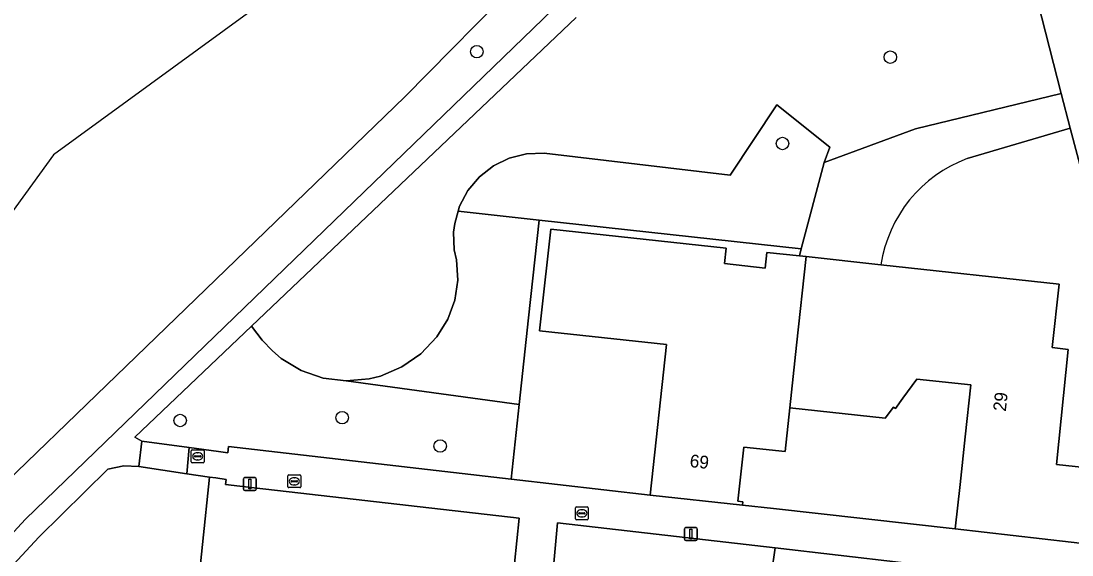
# Model space of a CAD drawing. Extents: x 162396 to 163643, y 386452 to 387406.
# Drawn here: x 162915.8 to 162998.1, y 387129.8 to 387171.5 of the extents above; entities that cross this region are included whole.
import ezdxf

# ---------------------------------------------------------------- set-up
doc = ezdxf.new("R2010")
doc.units = 0
for name, color, linetype in [('IMGEO_Boom', 7, 'Continuous'), ('IMGEO_Brandkraan', 7, 'Continuous'), ('IMGEO_Erf', 7, 'Continuous'), ('IMGEO_Groenvoorziening', 7, 'Continuous'), ('IMGEO_Lichtmast', 7, 'Continuous'), ('IMGEO_Meer_plas_ven_vijver', 7, 'Continuous'), ('IMGEO_Muur', 7, 'Continuous'), ('IMGEO_Pand', 7, 'Continuous'), ('IMGEO_Pand_nummerreeks', 7, 'Continuous'), ('IMGEO_Rioolput', 7, 'Continuous'), ('IMGEO_Voetpad_halfverhard', 7, 'Continuous'), ('IMGEO_Voetpad_open', 7, 'Continuous')]:
    doc.layers.add(name, color=color, linetype=linetype)

msp = doc.modelspace()

# ---------------------------------------------------------------- linework, layer by layer
at = {"layer": 'IMGEO_Boom'}
for centre in [(162951.492, 387169.124), (162983.842, 387168.702), (162975.411, 387161.953), (162928.28, 387140.296), (162940.961, 387140.515), (162948.63, 387138.296)]:
    msp.add_circle(centre, 0.489, dxfattribs=at)
at = {"layer": 'IMGEO_Brandkraan'}
for p, q in [((162929.155, 387137.072), (162929.155, 387137.924)), ((162929.23, 387137.998), (162930.082, 387137.998)), ((162929.414, 387137.492), (162929.414, 387137.504)), ((162929.852, 387137.455), (162929.454, 387137.455)), ((162929.457, 387137.541), (162929.855, 387137.541)), ((162929.643, 387137.778), (162929.668, 387137.778)), ((162929.898, 387137.504), (162929.898, 387137.492)), ((162930.156, 387137.924), (162930.156, 387137.072)), ((162930.082, 387136.998), (162929.23, 387136.998)), ((162929.666, 387137.218), (162929.641, 387137.218))]:
    msp.add_line(p, q, dxfattribs=at)
for points in [[(162929.155, 387137.072), (162929.155, 387137.924)], [(162929.23, 387137.998), (162930.082, 387137.998)], [(162930.156, 387137.924), (162930.156, 387137.072)], [(162930.082, 387136.998), (162929.23, 387136.998)]]:
    msp.add_lwpolyline(points, dxfattribs=at)
for centre, radius, start, end in [((162929.232, 387137.922), 0.0765, 91.55205, 178.44795), ((162929.232, 387137.922), 0.0765, 91.55205, 178.44795), ((162929.454, 387137.501), 0.0403, 85.87752, 175.75265), ((162929.451, 387137.491), 0.0366, 178.93798, 274.71019), ((162929.855, 387137.498), 0.043, 264.86636, 352.45326), ((162929.859, 387137.503), 0.0386, 1.73085, 96.63898), ((162930.08, 387137.922), 0.0765, 1.55205, 88.44795), ((162930.08, 387137.922), 0.0765, 1.55205, 88.44795), ((162929.232, 387137.074), 0.0765, 181.55205, 268.44795), ((162929.232, 387137.074), 0.0765, 181.55205, 268.44795), ((162930.08, 387137.074), 0.0765, 271.55205, 358.44795), ((162930.08, 387137.074), 0.0765, 271.55205, 358.44795)]:
    msp.add_arc(centre, radius, start, end, dxfattribs=at)
for centre, major_axis, ratio, start_param, end_param in [((162929.642, 387137.498), (-0.387, 0.002), 0.722429, 4.712389, 7.853982), ((162929.667, 387137.498), (-0.39, 0.002), 0.717154, 1.570796, 4.712389)]:
    msp.add_ellipse(centre, major_axis=major_axis, ratio=ratio, start_param=start_param, end_param=end_param, dxfattribs=at)
at = {"layer": 'IMGEO_Erf'}
for points in [[(162983.108, 387152.47), (162997.052, 387150.951), (162996.513, 387145.994), (162997.744, 387145.854), (162996.852, 387136.865), (162998.293, 387136.701), (163000.935, 387136.401), (163000.267, 387130.528), (163006.513, 387129.798), (163002.885, 387144.421), (162997.907, 387163.149)], [(162997.907, 387163.149), (162989.861, 387160.775)], [(163000, 387127.409), (162984.703, 387129.19), (162974.82, 387130.333), (162974.534, 387128.355), (162984.471, 387127.214), (162994.298, 387126.085), (162994.219, 387125.397), (162993.887, 387122.513), (162993.841, 387122.11), (162992.64, 387122.248), (162992.086, 387117.433), (162993.292, 387117.294), (162993.273, 387117.131), (162992.119, 387107.076), (162993.218, 387102.569), (162990.473, 387097.337), (162987.989, 387095.591), (162978.209, 387090.267), (162980.161, 387087.989), (162983.775, 387090.721), (162988.184, 387093.295), (162990.531, 387094.665), (163000, 387099.433)]]:
    msp.add_lwpolyline(points, dxfattribs=at)
for points in [[(162966.332, 387146.23), (162956.407, 387147.31), (162956.507, 387148.232), (162957.273, 387155.266), (162971.01, 387153.77), (162970.878, 387152.561), (162974.058, 387152.214), (162974.192, 387153.441), (162976.738, 387153.164), (162976.88, 387153.704), (162956.38, 387155.957), (162955.523, 387148.324), (162954.796, 387141.535), (162954.173, 387135.713), (162965.051, 387134.463)], [(162988.919, 387131.817), (162989.298, 387135.295), (162989.704, 387139.02), (162990.145, 387143.071), (162985.913, 387143.531), (162984.83, 387142.052), (162984.236, 387141.241), (162984.089, 387141.349), (162983.449, 387140.475), (162975.989, 387141.287), (162975.617, 387137.871), (162972.383, 387138.223), (162971.922, 387133.987), (162972.302, 387133.946), (162972.272, 387133.677), (162974.708, 387133.405)], [(162954.814, 387132.669), (162934.076, 387135.027), (162931.83, 387135.282), (162931.881, 387135.682), (162931.077, 387135.801), (162930.576, 387135.875), (162928.93, 387120.073), (162927.574, 387107.059), (162951.889, 387104.679), (162952.055, 387105.95), (162954.081, 387125.567)], [(162957.802, 387132.302), (162957.147, 387125.165), (162962.225, 387124.616), (162966.48, 387124.156), (162967.227, 387126.127), (162968.275, 387126.076), (162968.469, 387126.065), (162968.747, 387125.311), (162967.83, 387115.561), (162967.759, 387111.387), (162968.295, 387108.233), (162969.336, 387107.072), (162978.401, 387105.997), (162978.647, 387108.229), (162978.831, 387109.908), (162980.66, 387109.757), (162980.685, 387110.054), (162983.986, 387109.717), (162985.218, 387120.432), (162981.329, 387120.879), (162981.118, 387119.05), (162973.564, 387119.918), (162974.534, 387128.355), (162974.82, 387130.333)]]:
    msp.add_lwpolyline(points, close=True, dxfattribs=at)
msp.add_arc((162993.517, 387150.904), 10.526, 110.32286, 171.44632, dxfattribs=at)
at = {"layer": 'IMGEO_Groenvoorziening'}
for points in [[(162904.234, 387119.646), (162916.196, 387132.579), (162958.243, 387173.224), (162966.778, 387181.153), (162972.048, 387185.44), (162977.07, 387188.884), (162978.312, 387189.488), (162981.995, 387189.888), (162986.564, 387190.198), (162988.981, 387190.548), (162990.622, 387191.429), (162988.941, 387198.721), (162970.442, 387190.315), (162969.073, 387188.983), (162962.124, 387182.486), (162955.059, 387174.946), (162945.852, 387165.587), (162890.58, 387112.23)], [(162959.252, 387171.801), (162933.874, 387147.675), (162934.7, 387146.585), (162935.5, 387145.73), (162936.195, 387145.145), (162937.75, 387144.21), (162939.465, 387143.617), (162941.266, 387143.395), (162943.074, 387143.552), (162943.955, 387143.771), (162945.626, 387144.478), (162947.113, 387145.518), (162948.352, 387146.844), (162949.223, 387148.214), (162949.775, 387149.705), (162950.005, 387151.279), (162949.903, 387152.865), (162949.728, 387153.642), (162949.68, 387155.016), (162949.764, 387155.707), (162950.035, 387156.654), (162950.146, 387157.044), (162950.798, 387158.272), (162951.69, 387159.338), (162952.785, 387160.195), (162954.034, 387160.805), (162955.383, 387161.143), (162956.772, 387161.193), (162971.313, 387159.479), (162974.954, 387164.968), (162979.098, 387161.653), (162978.659, 387160.475), (162985.799, 387163.098), (162997.198, 387165.859), (162991.45, 387188.438)], [(162924.374, 387120.523), (162928.93, 387120.073), (162930.576, 387135.875), (162928.798, 387136.138), (162925.06, 387136.69), (162923.867, 387136.75), (162922.636, 387136.483), (162917.237, 387131.176), (162905.354, 387118.405)]]:
    msp.add_lwpolyline(points, dxfattribs=at)
for points in [[(162976.88, 387153.704), (162978.659, 387160.475), (162979.098, 387161.653), (162974.954, 387164.968), (162971.313, 387159.479), (162956.772, 387161.193), (162955.383, 387161.143), (162954.034, 387160.805), (162952.785, 387160.195), (162951.69, 387159.338), (162950.798, 387158.272), (162950.146, 387157.044), (162950.035, 387156.654), (162956.38, 387155.957)], [(162955.523, 387148.324), (162956.38, 387155.957), (162950.035, 387156.654), (162949.764, 387155.707), (162949.68, 387155.016), (162949.728, 387153.642), (162949.903, 387152.865), (162950.005, 387151.279), (162949.775, 387149.705), (162949.223, 387148.214), (162948.352, 387146.844), (162947.113, 387145.518), (162945.626, 387144.478), (162943.955, 387143.771), (162943.074, 387143.552), (162941.266, 387143.395), (162954.796, 387141.535)], [(162941.266, 387143.395), (162939.465, 387143.617), (162937.75, 387144.21), (162936.195, 387145.145), (162935.5, 387145.73), (162934.7, 387146.585), (162933.874, 387147.675), (162924.751, 387138.998), (162925.28, 387138.681), (162928.991, 387138.18), (162931.284, 387137.871), (162932.025, 387137.771), (162932.076, 387138.251), (162954.173, 387135.713), (162954.796, 387141.535)]]:
    msp.add_lwpolyline(points, close=True, dxfattribs=at)
at = {"layer": 'IMGEO_Lichtmast'}
for p, q in [((162933.336, 387135.827), (162934.126, 387135.827)), ((162934.126, 387135.827), (162933.336, 387135.827)), ((162933.236, 387134.927), (162933.236, 387135.727)), ((162933.236, 387135.727), (162933.236, 387134.927)), ((162934.226, 387135.727), (162934.226, 387134.927)), ((162934.226, 387134.927), (162934.226, 387135.727)), ((162934.126, 387134.827), (162933.336, 387134.827)), ((162933.336, 387134.827), (162934.126, 387134.827)), ((162967.749, 387131.02), (162967.749, 387131.82)), ((162967.749, 387131.82), (162967.749, 387131.02)), ((162967.849, 387131.92), (162968.639, 387131.92)), ((162968.639, 387131.92), (162967.849, 387131.92)), ((162968.739, 387131.82), (162968.739, 387131.02)), ((162968.739, 387131.02), (162968.739, 387131.82)), ((162968.639, 387130.92), (162967.849, 387130.92)), ((162967.849, 387130.92), (162968.639, 387130.92))]:
    msp.add_line(p, q, dxfattribs=at)
for points in [[(162933.656, 387135.702), (162933.806, 387135.702), (162933.806, 387134.952), (162933.656, 387134.952), (162933.656, 387135.702)], [(162968.169, 387131.795), (162968.319, 387131.795), (162968.319, 387131.045), (162968.169, 387131.045), (162968.169, 387131.795)]]:
    msp.add_lwpolyline(points, dxfattribs=at)
for centre, start, end in [((162933.336, 387135.727), 90, 180), ((162933.336, 387135.727), 90, 180), ((162934.126, 387135.727), 0, 90), ((162934.126, 387135.727), 360, 90), ((162933.336, 387134.927), 180, 270), ((162933.336, 387134.927), 180, 270), ((162934.126, 387134.927), 270, 0), ((162934.126, 387134.927), 270, 0), ((162967.849, 387131.82), 90, 180), ((162967.849, 387131.82), 90, 180), ((162968.639, 387131.82), 0, 90), ((162968.639, 387131.82), 360, 90), ((162967.849, 387131.02), 180, 270), ((162967.849, 387131.02), 180, 270), ((162968.639, 387131.02), 270, 0), ((162968.639, 387131.02), 270, 0)]:
    msp.add_arc(centre, 0.1, start, end, dxfattribs=at)
at = {"layer": 'IMGEO_Meer_plas_ven_vijver'}
msp.add_lwpolyline([(162890.58, 387112.23), (162945.852, 387165.587), (162955.059, 387174.946), (162962.124, 387182.486), (162969.073, 387188.983), (162970.442, 387190.315), (162971.638, 387191.805), (162973.104, 387194.354), (162973.352, 387194.938), (162973.548, 387195.542), (162973.688, 387196.162), (162973.773, 387196.791), (162973.801, 387197.425), (162973.772, 387198.059), (162973.686, 387198.688), (162973.682, 387198.713), (162973.321, 387201.081), (162973.321, 387201.081), (162918.383, 387161.062), (162747.703, 386925.615)], dxfattribs=at)
at = {"layer": 'IMGEO_Muur'}
for points in [[(162956.38, 387155.957), (162955.523, 387148.324)], [(162954.173, 387135.713), (162965.051, 387134.463)], [(162974.708, 387133.405), (162988.919, 387131.817)]]:
    msp.add_lwpolyline(points, dxfattribs=at)
at = {"layer": 'IMGEO_Pand'}
for points in [[(162976.738, 387153.164), (162974.192, 387153.441), (162974.058, 387152.214), (162970.878, 387152.561), (162971.01, 387153.77), (162957.273, 387155.266), (162956.507, 387148.232), (162956.407, 387147.31), (162966.332, 387146.23), (162965.051, 387134.463), (162972.272, 387133.677), (162972.302, 387133.946), (162971.922, 387133.987), (162972.383, 387138.223), (162975.617, 387137.871), (162975.989, 387141.287), (162976.5, 387146.183), (162977.254, 387153.107)], [(163000.267, 387130.528), (163000.935, 387136.401), (162998.293, 387136.701), (162996.852, 387136.865), (162997.744, 387145.854), (162996.513, 387145.994), (162997.052, 387150.951), (162983.108, 387152.47), (162977.254, 387153.107), (162976.5, 387146.183), (162975.989, 387141.287), (162983.449, 387140.475), (162984.089, 387141.349), (162984.236, 387141.241), (162984.83, 387142.052), (162985.913, 387143.531), (162990.145, 387143.071), (162989.704, 387139.02), (162989.298, 387135.295), (162988.919, 387131.817)]]:
    msp.add_lwpolyline(points, close=True, dxfattribs=at)
at = {"layer": 'IMGEO_Rioolput'}
for p, q in [((162936.713, 387135.12), (162936.713, 387135.972)), ((162936.788, 387136.046), (162937.64, 387136.046)), ((162937.201, 387135.826), (162937.226, 387135.826)), ((162937.714, 387135.972), (162937.714, 387135.12)), ((162937.64, 387135.046), (162936.788, 387135.046)), ((162936.972, 387135.54), (162936.972, 387135.552)), ((162937.41, 387135.503), (162937.012, 387135.503)), ((162937.015, 387135.589), (162937.413, 387135.589)), ((162937.224, 387135.266), (162937.199, 387135.266)), ((162937.456, 387135.552), (162937.456, 387135.54)), ((162959.211, 387132.608), (162959.211, 387133.46)), ((162959.286, 387133.534), (162960.138, 387133.534)), ((162959.699, 387133.314), (162959.724, 387133.314)), ((162960.212, 387133.46), (162960.212, 387132.608)), ((162960.138, 387132.534), (162959.286, 387132.534)), ((162959.47, 387133.028), (162959.47, 387133.04)), ((162959.908, 387132.991), (162959.51, 387132.991)), ((162959.513, 387133.077), (162959.911, 387133.077)), ((162959.722, 387132.754), (162959.697, 387132.754)), ((162959.954, 387133.04), (162959.954, 387133.028))]:
    msp.add_line(p, q, dxfattribs=at)
for points in [[(162936.713, 387135.12), (162936.713, 387135.972)], [(162936.788, 387136.046), (162937.64, 387136.046)], [(162937.714, 387135.972), (162937.714, 387135.12)], [(162937.64, 387135.046), (162936.788, 387135.046)], [(162959.211, 387132.608), (162959.211, 387133.46)], [(162959.286, 387133.534), (162960.138, 387133.534)], [(162960.212, 387133.46), (162960.212, 387132.608)], [(162960.138, 387132.534), (162959.286, 387132.534)]]:
    msp.add_lwpolyline(points, dxfattribs=at)
for centre, radius, start, end in [((162936.79, 387135.97), 0.0765, 91.55205, 178.44795), ((162936.79, 387135.97), 0.0765, 91.55205, 178.44795), ((162937.638, 387135.97), 0.0765, 1.55205, 88.44795), ((162937.638, 387135.97), 0.0765, 1.55205, 88.44795), ((162936.79, 387135.122), 0.0765, 181.55205, 268.44795), ((162936.79, 387135.122), 0.0765, 181.55205, 268.44795), ((162937.012, 387135.549), 0.0403, 85.87752, 175.75265), ((162937.009, 387135.539), 0.0366, 178.93798, 274.71019), ((162937.413, 387135.546), 0.043, 264.86636, 352.45326), ((162937.417, 387135.551), 0.0386, 1.73085, 96.63898), ((162937.638, 387135.122), 0.0765, 271.55205, 358.44795), ((162937.638, 387135.122), 0.0765, 271.55205, 358.44795), ((162959.288, 387133.458), 0.0765, 91.55205, 178.44795), ((162959.288, 387133.458), 0.0765, 91.55205, 178.44795), ((162960.136, 387133.458), 0.0765, 1.55205, 88.44795), ((162960.136, 387133.458), 0.0765, 1.55205, 88.44795), ((162959.288, 387132.61), 0.0765, 181.55205, 268.44795), ((162959.288, 387132.61), 0.0765, 181.55205, 268.44795), ((162959.51, 387133.037), 0.0403, 85.87752, 175.75265), ((162959.507, 387133.027), 0.0366, 178.93798, 274.71019), ((162959.911, 387133.034), 0.043, 264.86636, 352.45326), ((162959.915, 387133.039), 0.0386, 1.73085, 96.63898), ((162960.136, 387132.61), 0.0765, 271.55205, 358.44795), ((162960.136, 387132.61), 0.0765, 271.55205, 358.44795)]:
    msp.add_arc(centre, radius, start, end, dxfattribs=at)
for centre, major_axis, ratio, start_param, end_param in [((162937.2, 387135.546), (-0.387, 0.002), 0.722429, 4.712389, 7.853982), ((162937.225, 387135.546), (-0.39, 0.002), 0.717154, 1.570796, 4.712389), ((162959.698, 387133.034), (-0.387, 0.002), 0.722429, 4.712389, 7.853982), ((162959.723, 387133.034), (-0.39, 0.002), 0.717154, 1.570796, 4.712389)]:
    msp.add_ellipse(centre, major_axis=major_axis, ratio=ratio, start_param=start_param, end_param=end_param, dxfattribs=at)
at = {"layer": 'IMGEO_Voetpad_halfverhard'}
for points in [[(162958.243, 387173.224), (162916.196, 387132.579), (162904.234, 387119.646)], [(162905.354, 387118.405), (162917.237, 387131.176), (162922.636, 387136.483), (162923.867, 387136.75), (162925.06, 387136.69), (162925.28, 387138.681), (162924.751, 387138.998), (162933.874, 387147.675), (162959.252, 387171.801)]]:
    msp.add_lwpolyline(points, dxfattribs=at)
at = {"layer": 'IMGEO_Voetpad_open'}
for points in [[(162986.23, 387210.485), (162986.356, 387209.887), (162988.941, 387198.721), (162990.622, 387191.429), (162991.45, 387188.438), (162997.198, 387165.859), (162997.907, 387163.149), (163002.885, 387144.421), (163006.513, 387129.798), (163007.387, 387126.313), (163011.824, 387109.13)], [(162989.861, 387160.775), (162997.907, 387163.149), (162997.198, 387165.859), (162985.799, 387163.098), (162978.659, 387160.475), (162976.88, 387153.704), (162976.738, 387153.164), (162977.254, 387153.107), (162983.108, 387152.47)], [(163000.267, 387130.528), (162988.919, 387131.817), (162974.708, 387133.405), (162972.272, 387133.677), (162965.051, 387134.463), (162954.173, 387135.713), (162932.076, 387138.251), (162932.025, 387137.771), (162931.284, 387137.871), (162928.991, 387138.18), (162928.798, 387136.138), (162930.576, 387135.875), (162931.077, 387135.801), (162931.881, 387135.682), (162931.83, 387135.282), (162934.076, 387135.027), (162954.814, 387132.669), (162954.081, 387125.567), (162957.147, 387125.165), (162957.802, 387132.302), (162974.82, 387130.333), (162984.703, 387129.19), (163000, 387127.409)]]:
    msp.add_lwpolyline(points, dxfattribs=at)
msp.add_lwpolyline([(162928.991, 387138.18), (162925.28, 387138.681), (162925.06, 387136.69), (162928.798, 387136.138)], close=True, dxfattribs=at)
msp.add_arc((162993.517, 387150.904), 10.526, 110.32286, 171.44632, dxfattribs=at)

# ---------------------------------------------------------------- texts
at = {"layer": 'IMGEO_Pand_nummerreeks'}
for s, rotation, p in [('29', 83.78417, (162992.874, 387140.972)), ('69', 353.78786, (162968.113, 387136.665))]:
    msp.add_text(s, height=1, rotation=rotation, dxfattribs=at).set_placement(p)

doc.saveas('drawing.dxf')
